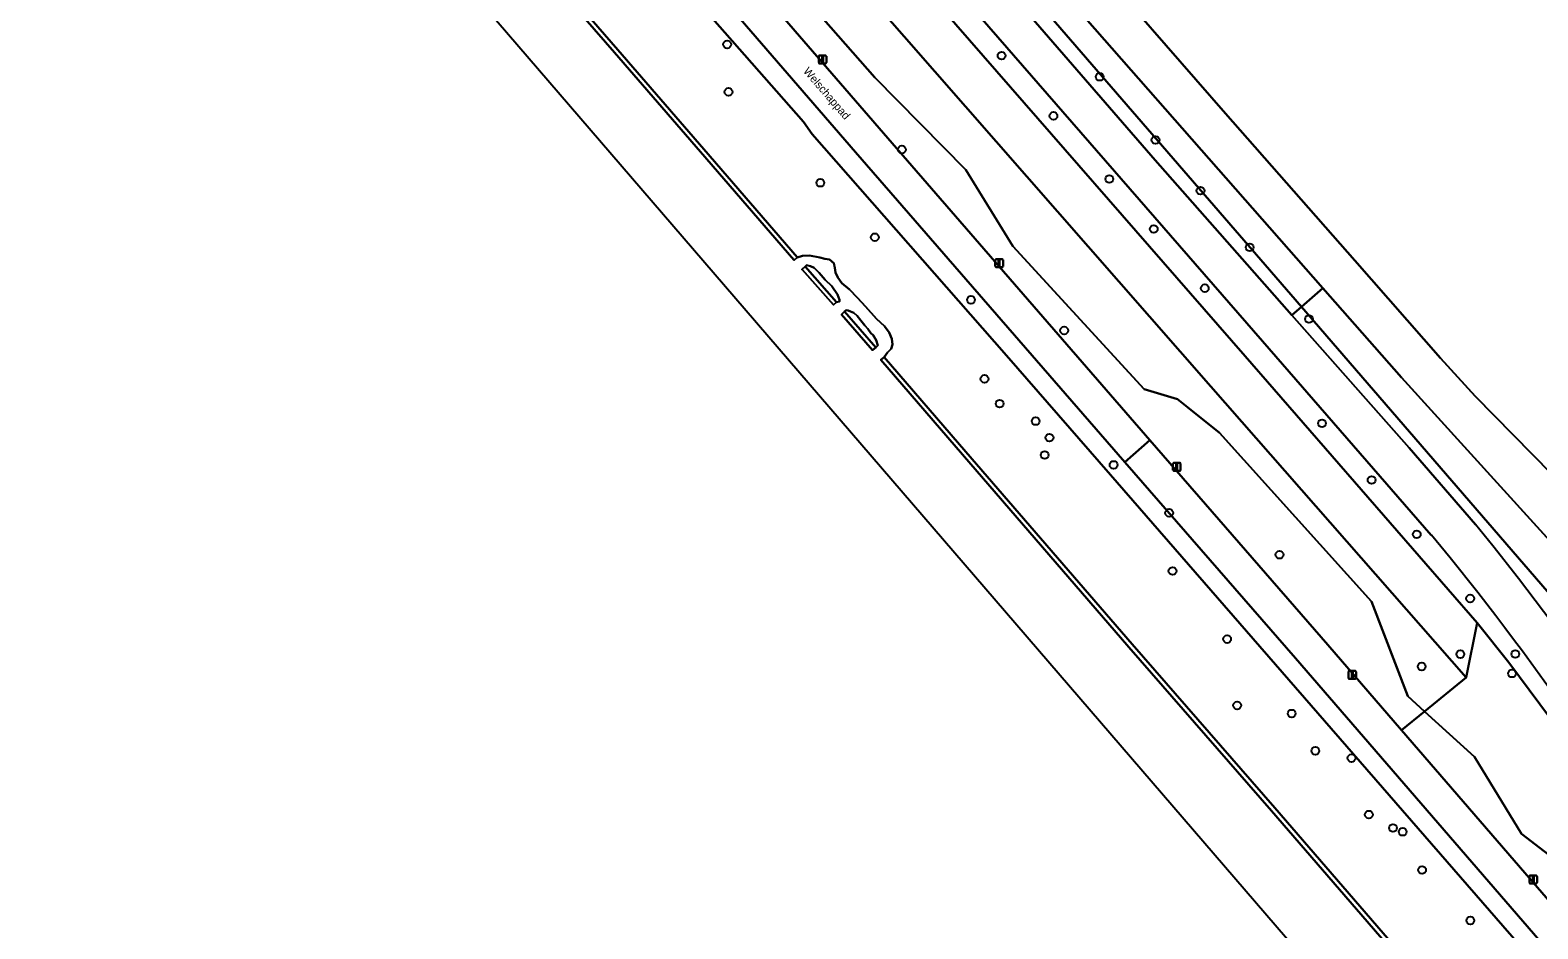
# Model space of a CAD drawing. Extents: x 155209 to 156748, y 385356 to 388487.
# Drawn here: x 155777.4 to 155966.9, y 385502.8 to 385615.9 of the extents above; entities that cross this region are included whole.
import ezdxf

# ---------------------------------------------------------------- set-up
doc = ezdxf.new("R2010")
doc.units = 0
for name, color, linetype in [('IMGEO_Berm_groen', 7, 'Continuous'), ('IMGEO_Boom', 7, 'Continuous'), ('IMGEO_Fietspad_gesloten', 7, 'Continuous'), ('IMGEO_Gemengd_bos', 7, 'Continuous'), ('IMGEO_Groenvoorziening', 7, 'Continuous'), ('IMGEO_Kademuur', 7, 'Continuous'), ('IMGEO_Lichtmast', 7, 'Continuous'), ('IMGEO_Loofbos', 7, 'Continuous'), ('IMGEO_Oever', 7, 'Continuous'), ('IMGEO_Openbare_ruimte_label', 7, 'Continuous'), ('IMGEO_Rijbaan_lokaal_gesloten', 7, 'Continuous'), ('IMGEO_Waterloop', 7, 'Continuous')]:
    doc.layers.add(name, color=color, linetype=linetype)

msp = doc.modelspace()

# ---------------------------------------------------------------- linework, layer by layer
at = {"layer": 'IMGEO_Berm_groen'}
for points in [[(155782.07, 385749.03), (155782.06, 385749.04), (155781.96, 385748.95), (155782.85, 385747.95), (155780.5, 385745.88), (155787.45, 385737.87), (155791.34, 385733.72), (155816.07, 385705.59), (155827.38, 385692.36), (155852.69, 385663.67), (155859.69, 385656.07), (155892.08, 385618.52), (155930.14, 385574.84), (155959.32, 385541.34), (155963.31, 385536.34), (155969.74, 385527.64)], [(155953.55, 385552.36), (155932.32, 385576.76), (155858.46, 385661.65), (155782.07, 385749.03)], [(155777.86, 385715.13), (155782.52, 385709.35), (155785.67, 385706.23), (155793.08, 385698.9), (155800.98, 385689.95), (155804.16, 385686.65), (155806.27, 385683.98), (155807.67, 385681.86), (155810.16, 385678.73), (155813.26, 385675.28), (155814.49, 385673.96), (155824.14, 385662.7), (155832.07, 385653.89), (155839, 385645.25), (155843.23, 385640.36), (155844.26, 385638.91), (155847.26, 385635.93), (155853.11, 385629.55), (155856.72, 385624.72), (155874.64, 385604.33), (155875.73, 385602.78), (155900.15, 385574.95), (155913.21, 385559.93), (155965.33, 385500)], [(155915.04, 385561.54), (155881.17, 385600.52), (155801.14, 385693.08)], [(155815.7, 385682.65), (155885.24, 385602.25), (155918.18, 385564.31), (155940.55, 385538.54), (155949.82, 385527.82), (155952.7, 385530.17), (155950.59, 385532.09), (155946.03, 385544), (155926.93, 385565.21), (155922.9, 385568.46), (155921.66, 385569.46), (155917.45, 385570.69), (155900.94, 385588.67), (155895.02, 385598.3), (155883.59, 385609.91), (155865.17, 385630.9)], [(155969.69, 385543.44), (155937.21, 385581.04), (155936.02, 385580.01), (155950.77, 385563.31), (155959.1, 385553.69)], [(155996.54, 385467.34), (155936.48, 385536.87), (155915.04, 385561.54)], [(155970.68, 385510.35), (155964.88, 385514.77), (155958.99, 385524.46), (155952.7, 385530.17), (155949.82, 385527.82), (155999.26, 385470.62)]]:
    msp.add_lwpolyline(points, dxfattribs=at)
msp.add_lwpolyline([(155886.95, 385639.23), (155855.07, 385676.14), (155845.61, 385686.83), (155844.88, 385684.53), (155899.68, 385621.64), (155918.84, 385599.48), (155936.02, 385580.01), (155937.21, 385581.04)], close=True, dxfattribs=at)
for centre, radius, start, end in [((155696.85, 385340.26), 338.13, 29.728, 39.1393), ((155692.7, 385336.3), 338.71, 29.5861, 39.6339)]:
    msp.add_arc(centre, radius, start, end, dxfattribs=at)
at = {"layer": 'IMGEO_Boom'}
for centre in [(155865.04, 385614.05), (155899.53, 385612.65), (155911.86, 385609.99), (155865.2, 385608.09), (155906.05, 385605.07), (155918.88, 385602.04), (155886.99, 385600.84), (155876.74, 385596.66), (155913.07, 385597.13), (155924.53, 385595.66), (155918.66, 385590.84), (155883.6, 385589.81), (155930.72, 385588.55), (155925.07, 385583.4), (155895.68, 385581.94), (155938.17, 385579.52), (155907.4, 385578.08), (155897.38, 385572), (155899.29, 385568.88), (155903.81, 385566.69), (155939.81, 385566.41), (155905.55, 385564.61), (155904.95, 385562.42), (155913.61, 385561.18), (155946.04, 385559.29), (155920.59, 385555.15), (155951.72, 385552.45), (155934.46, 385549.88), (155921.02, 385547.83), (155958.43, 385544.38), (155927.88, 385539.27), (155957.2, 385537.38), (155964.1, 385537.4), (155952.34, 385535.83), (155963.68, 385534.96), (155929.14, 385530.93), (155936, 385529.91), (155938.97, 385525.22), (155943.51, 385524.31), (155945.69, 385517.21), (155948.73, 385515.53), (155949.95, 385515.05), (155952.39, 385510.25), (155958.46, 385503.89)]:
    msp.add_circle(centre, 0.489, dxfattribs=at)
at = {"layer": 'IMGEO_Fietspad_gesloten'}
for points in [[(155801.14, 385693.08), (155881.17, 385600.52), (155915.04, 385561.54), (155918.18, 385564.31), (155885.24, 385602.25), (155815.7, 385682.65)], [(155918.18, 385564.31), (155915.04, 385561.54), (155936.48, 385536.87), (155996.54, 385467.34)], [(155999.26, 385470.62), (155949.82, 385527.82), (155940.55, 385538.54), (155918.18, 385564.31)]]:
    msp.add_lwpolyline(points, dxfattribs=at)
at = {"layer": 'IMGEO_Gemengd_bos'}
for points in [[(155966.94, 385689.13), (155932.32, 385658.31), (155888.87, 385701.04), (155874.49, 385691.04), (155869.08, 385697.58), (155868.93, 385697.76), (155862.24, 385695.33), (155854.73, 385693.22), (155851.78, 385692.17), (155887.19, 385651.49), (155891.3, 385647.45), (155901.59, 385635.34), (155927.68, 385605.37), (155943.93, 385586.89), (155954.72, 385574.62), (155959.07, 385569.83), (155978.29, 385550.24)], [(155978.29, 385550.24), (155959.07, 385569.83), (155954.72, 385574.62), (155943.93, 385586.89), (155927.68, 385605.37), (155901.59, 385635.34), (155891.3, 385647.45), (155887.19, 385651.49), (155851.78, 385692.17), (155850.05, 385691.56), (155847.34, 385690.32), (155848.14, 385689.39), (155861.07, 385674.68), (155865.58, 385669.32), (155882.05, 385650.94), (155889.67, 385641.14), (155898.13, 385630.99), (155939.92, 385583.4), (155949.78, 385572.17), (156000, 385516.89)], [(156025.9, 385490.76), (156023.36, 385493.17), (156018.2, 385497.64), (156016.48, 385498.76), (156015.35, 385500), (156000, 385516.89), (155949.78, 385572.17), (155939.92, 385583.4), (155937.21, 385581.04), (155969.69, 385543.44)]]:
    msp.add_lwpolyline(points, dxfattribs=at)
at = {"layer": 'IMGEO_Groenvoorziening'}
for points in [[(155859.69, 385656.07), (155852.69, 385663.67), (155827.38, 385692.36), (155816.07, 385705.59), (155791.34, 385733.72), (155787.45, 385737.87), (155780.5, 385745.88), (155778.36, 385743.99), (155782.11, 385737.88), (155784.14, 385735.45), (155786.95, 385731.61), (155788.09, 385730.32), (155789.13, 385728.5), (155796.23, 385719.42), (155812.62, 385700.37), (155814.03, 385698.73), (155925.85, 385571.06), (155957.92, 385534.44), (155959.32, 385541.34), (155930.14, 385574.84), (155892.08, 385618.52)], [(155865.58, 385669.32), (155861.07, 385674.68), (155848.14, 385689.39), (155847.34, 385690.32), (155846.63, 385689.99), (155845.61, 385686.83), (155855.07, 385676.14), (155886.95, 385639.23), (155937.21, 385581.04), (155939.92, 385583.4), (155898.13, 385630.99), (155889.67, 385641.14), (155882.05, 385650.94)], [(155959.32, 385541.34), (155957.92, 385534.44), (155952.7, 385530.17), (155958.99, 385524.46), (155964.88, 385514.77), (155970.68, 385510.35), (155976.57, 385506.1), (155984.38, 385497.1), (155985.82, 385492.14), (155986.88, 385487.05), (155991.84, 385485.14), (155998.86, 385476.6), (156000.73, 385471.89), (156003.21, 385473.28), (155993.8, 385489.13), (155989.34, 385496.95), (155974.16, 385521.91), (155969.74, 385527.64), (155963.31, 385536.34)]]:
    msp.add_lwpolyline(points, close=True, dxfattribs=at)
msp.add_lwpolyline([(155865.17, 385630.9), (155883.59, 385609.91), (155895.02, 385598.3), (155900.94, 385588.67), (155917.45, 385570.69), (155921.66, 385569.46), (155922.9, 385568.46), (155926.93, 385565.21), (155946.03, 385544), (155950.59, 385532.09), (155952.7, 385530.17), (155957.92, 385534.44), (155925.85, 385571.06), (155814.03, 385698.73)], dxfattribs=at)
at = {"layer": 'IMGEO_Kademuur'}
for points in [[(155873.85, 385587.28), (155873.82, 385587.31), (155862.09, 385600.89), (155851.31, 385613.39), (155834.83, 385632.36), (155822.6, 385646.55), (155808.94, 385662.37), (155799.84, 385672.92), (155795.79, 385677.61), (155794.93, 385678.6), (155793.59, 385680.16), (155793.17, 385679.8), (155799.42, 385672.56), (155808.53, 385662.01), (155822.18, 385646.19), (155834.42, 385632), (155850.89, 385613.03), (155861.67, 385600.54), (155873.4, 385586.95), (155873.44, 385586.91)], [(155874.86, 385586.12), (155874.43, 385585.77), (155874.45, 385585.75), (155878.39, 385581.29), (155878.8, 385581.65), (155874.86, 385586.11)], [(155879.39, 385580.09), (155883.31, 385575.6), (155883.73, 385575.96), (155879.8, 385580.45)], [(155884.79, 385574.73), (155884.37, 385574.38), (155894.6, 385562.47), (155915.54, 385538.26), (155933.45, 385517.7), (155957.77, 385489.57), (155974, 385471), (155974.41, 385471.36), (155973.77, 385472.1), (155972.26, 385473.82), (155958.18, 385489.93), (155933.87, 385518.06), (155915.96, 385538.62), (155895.02, 385562.83)]]:
    msp.add_lwpolyline(points, close=True, dxfattribs=at)
at = {"layer": 'IMGEO_Lichtmast'}
for p, q in [((155876.54, 385611.77), (155876.54, 385612.57)), ((155876.54, 385612.57), (155876.54, 385611.77)), ((155876.64, 385612.67), (155877.43, 385612.67)), ((155877.43, 385612.67), (155876.64, 385612.67)), ((155877.43, 385611.67), (155876.64, 385611.67)), ((155876.64, 385611.67), (155877.43, 385611.67)), ((155877.53, 385612.57), (155877.53, 385611.77)), ((155877.53, 385611.77), (155877.53, 385612.57)), ((155898.72, 385586.15), (155898.72, 385586.95)), ((155898.72, 385586.95), (155898.72, 385586.15)), ((155898.82, 385587.05), (155899.61, 385587.05)), ((155899.61, 385587.05), (155898.82, 385587.05)), ((155899.71, 385586.95), (155899.71, 385586.15)), ((155899.71, 385586.15), (155899.71, 385586.95)), ((155899.61, 385586.05), (155898.82, 385586.05)), ((155898.82, 385586.05), (155899.61, 385586.05)), ((155921.05, 385560.53), (155921.05, 385561.33)), ((155921.05, 385561.33), (155921.05, 385560.53)), ((155921.15, 385561.43), (155921.94, 385561.43)), ((155921.94, 385561.43), (155921.15, 385561.43)), ((155921.94, 385560.43), (155921.15, 385560.43)), ((155921.15, 385560.43), (155921.94, 385560.43)), ((155922.04, 385561.33), (155922.04, 385560.53)), ((155922.04, 385560.53), (155922.04, 385561.33)), ((155943.12, 385534.38), (155943.12, 385535.18)), ((155943.12, 385535.18), (155943.12, 385534.38)), ((155943.22, 385535.28), (155944.01, 385535.28)), ((155944.01, 385535.28), (155943.22, 385535.28)), ((155944.01, 385534.28), (155943.22, 385534.28)), ((155943.22, 385534.28), (155944.01, 385534.28)), ((155944.11, 385535.18), (155944.11, 385534.38)), ((155944.11, 385534.38), (155944.11, 385535.18)), ((155965.87, 385508.65), (155965.87, 385509.44)), ((155965.87, 385509.44), (155965.87, 385508.65)), ((155965.97, 385509.54), (155966.76, 385509.54)), ((155966.76, 385509.54), (155965.97, 385509.54)), ((155966.86, 385509.44), (155966.86, 385508.65)), ((155966.86, 385508.65), (155966.86, 385509.44)), ((155966.76, 385508.55), (155965.97, 385508.55)), ((155965.97, 385508.55), (155966.76, 385508.55))]:
    msp.add_line(p, q, dxfattribs=at)
for points in [[(155876.96, 385612.55), (155877.11, 385612.55), (155877.11, 385611.8), (155876.96, 385611.8), (155876.96, 385612.55)], [(155899.14, 385586.92), (155899.29, 385586.92), (155899.29, 385586.17), (155899.14, 385586.17), (155899.14, 385586.92)], [(155921.47, 385561.3), (155921.62, 385561.3), (155921.62, 385560.55), (155921.47, 385560.55), (155921.47, 385561.3)], [(155943.54, 385535.15), (155943.69, 385535.15), (155943.69, 385534.4), (155943.54, 385534.4), (155943.54, 385535.15)], [(155966.29, 385509.42), (155966.44, 385509.42), (155966.44, 385508.67), (155966.29, 385508.67), (155966.29, 385509.42)]]:
    msp.add_lwpolyline(points, dxfattribs=at)
for centre, start, end in [((155876.64, 385612.57), 90, 180), ((155876.64, 385612.57), 90, 180), ((155876.64, 385611.77), 180, 270), ((155876.64, 385611.77), 180, 270), ((155877.43, 385612.57), 0, 90), ((155877.43, 385612.57), 360, 90), ((155877.43, 385611.77), 270, 0), ((155877.43, 385611.77), 270, 0), ((155898.82, 385586.95), 90, 180), ((155898.82, 385586.95), 90, 180), ((155899.61, 385586.95), 0, 90), ((155899.61, 385586.95), 360, 90), ((155898.82, 385586.15), 180, 270), ((155898.82, 385586.15), 180, 270), ((155899.61, 385586.15), 270, 0), ((155899.61, 385586.15), 270, 0), ((155921.15, 385561.33), 90, 180), ((155921.15, 385561.33), 90, 180), ((155921.15, 385560.53), 180, 270), ((155921.15, 385560.53), 180, 270), ((155921.94, 385561.33), 0, 90), ((155921.94, 385561.33), 360, 90), ((155921.94, 385560.53), 270, 0), ((155921.94, 385560.53), 270, 0), ((155943.22, 385535.18), 90, 180), ((155943.22, 385535.18), 90, 180), ((155943.22, 385534.38), 180, 270), ((155943.22, 385534.38), 180, 270), ((155944.01, 385535.18), 0, 90), ((155944.01, 385535.18), 360, 90), ((155944.01, 385534.38), 270, 0), ((155944.01, 385534.38), 270, 0), ((155965.97, 385509.44), 90, 180), ((155965.97, 385509.44), 90, 180), ((155966.76, 385509.44), 0, 90), ((155966.76, 385509.44), 360, 90), ((155965.97, 385508.65), 180, 270), ((155965.97, 385508.65), 180, 270), ((155966.76, 385508.65), 270, 0), ((155966.76, 385508.65), 270, 0)]:
    msp.add_arc(centre, 0.1, start, end, dxfattribs=at)
at = {"layer": 'IMGEO_Loofbos'}
for points in [[(155972.92, 385492.24), (155965.33, 385500), (155913.21, 385559.93), (155900.15, 385574.95), (155875.73, 385602.78), (155874.64, 385604.33), (155856.72, 385624.72), (155853.11, 385629.55), (155847.26, 385635.93), (155844.26, 385638.91), (155843.23, 385640.36), (155839, 385645.25), (155832.07, 385653.89), (155824.14, 385662.7), (155814.49, 385673.96), (155807.18, 385667.54), (155806.1, 385668.83), (155813.26, 385675.28), (155810.16, 385678.73), (155807.67, 385681.86)], [(155834.83, 385632.36), (155851.31, 385613.39), (155862.09, 385600.89), (155873.82, 385587.31), (155873.85, 385587.28), (155874.52, 385587.49), (155875.39, 385587.5), (155876.67, 385587.28), (155877.31, 385587.09), (155877.89, 385587.03), (155878.44, 385586.54), (155878.58, 385585.98), (155878.66, 385585.39), (155878.96, 385584.73), (155879.46, 385584.05), (155880.43, 385583.22), (155881.42, 385582.18), (155882.43, 385581.08), (155883.79, 385579.55), (155884.83, 385578.62), (155885.4, 385577.85), (155885.72, 385577.03), (155885.83, 385576.32), (155885.64, 385575.78), (155885.19, 385575.31), (155884.79, 385574.73), (155895.02, 385562.83), (155915.96, 385538.62), (155933.87, 385518.06), (155958.18, 385489.93)]]:
    msp.add_lwpolyline(points, dxfattribs=at)
at = {"layer": 'IMGEO_Oever'}
for points in [[(155874.86, 385586.11), (155878.8, 385581.65), (155879.16, 385581.74), (155879.16, 385581.93), (155878.89, 385582.62), (155878.18, 385583.64), (155877.37, 385584.47), (155876.61, 385585.34), (155875.99, 385585.95), (155875.5, 385586.18), (155875.03, 385586.3)], [(155879.8, 385580.45), (155883.73, 385575.96), (155883.96, 385576.18), (155883.77, 385576.85), (155883.4, 385577.49), (155883.09, 385577.74), (155882.71, 385578.31), (155882.35, 385578.72), (155881.85, 385579.34), (155881.36, 385579.94), (155880.96, 385580.32), (155880.54, 385580.45), (155880.23, 385580.59), (155880, 385580.63)]]:
    msp.add_lwpolyline(points, close=True, dxfattribs=at)
at = {"layer": 'IMGEO_Rijbaan_lokaal_gesloten'}
msp.add_lwpolyline([(155959.1, 385553.69), (155950.77, 385563.31), (155936.02, 385580.01), (155918.84, 385599.48), (155899.68, 385621.64), (155844.88, 385684.53), (155834.55, 385696.38), (155833.92, 385697.1), (155810.7, 385723.74), (155790.5, 385746.92), (155787.77, 385749.85), (155787.5, 385750.14), (155787.41, 385750.24), (155785.71, 385752.29), (155782.06, 385749.04), (155782.07, 385749.03), (155858.46, 385661.65), (155932.32, 385576.76), (155953.55, 385552.36)], dxfattribs=at)
for centre, radius, start, end in [((155696.85, 385340.26), 338.13, 29.728, 39.1393), ((155692.7, 385336.3), 338.71, 29.5861, 39.6339)]:
    msp.add_arc(centre, radius, start, end, dxfattribs=at)
at = {"layer": 'IMGEO_Waterloop'}
for points in [[(155338.36, 386882.5), (155347.75, 386593.46), (155372.17, 386452.99), (155407.28, 386304.88), (155468.02, 386140.85), (155529.79, 386009.21), (155656.16, 385826.03), (155736.49, 385732.72), (156047.64, 385371.29), (156061.16, 385355.59)], [(155957.77, 385489.57), (155933.45, 385517.7), (155915.54, 385538.26), (155894.6, 385562.47), (155884.37, 385574.38), (155884.79, 385574.73), (155885.19, 385575.31), (155885.64, 385575.78), (155885.83, 385576.32), (155885.72, 385577.03), (155885.4, 385577.85), (155884.83, 385578.62), (155883.79, 385579.55), (155882.43, 385581.08), (155881.42, 385582.18), (155880.43, 385583.22), (155879.46, 385584.05), (155878.96, 385584.73), (155878.66, 385585.39), (155878.58, 385585.98), (155878.44, 385586.54), (155877.89, 385587.03), (155877.31, 385587.09), (155876.67, 385587.28), (155875.39, 385587.5), (155874.52, 385587.49), (155873.85, 385587.28), (155873.44, 385586.91), (155873.4, 385586.95), (155861.67, 385600.54), (155850.89, 385613.03), (155834.42, 385632)]]:
    msp.add_lwpolyline(points, dxfattribs=at)
for points in [[(155878.18, 385583.64), (155878.89, 385582.62), (155879.16, 385581.93), (155879.16, 385581.74), (155878.8, 385581.65), (155878.39, 385581.29), (155874.45, 385585.75), (155874.43, 385585.77), (155874.86, 385586.12), (155874.86, 385586.11), (155875.03, 385586.3), (155875.5, 385586.18), (155875.99, 385585.95), (155876.61, 385585.34), (155877.37, 385584.47)], [(155880.23, 385580.59), (155880.54, 385580.45), (155880.96, 385580.32), (155881.36, 385579.94), (155881.85, 385579.34), (155882.35, 385578.72), (155882.71, 385578.31), (155883.09, 385577.74), (155883.4, 385577.49), (155883.77, 385576.85), (155883.96, 385576.18), (155883.73, 385575.96), (155883.31, 385575.6), (155879.39, 385580.09), (155879.8, 385580.45), (155880, 385580.63)]]:
    msp.add_lwpolyline(points, close=True, dxfattribs=at)

# ---------------------------------------------------------------- texts
at = {"layer": 'IMGEO_Openbare_ruimte_label'}
msp.add_text('Welschappad', height=1, rotation=310.8249, dxfattribs=at).set_placement((155874.54, 385610.64))

doc.saveas('drawing.dxf')
